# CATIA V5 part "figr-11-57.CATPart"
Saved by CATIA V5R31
Part number: Part1
Bounding box of the stored display mesh (mm): x -55 to 55, y -105 to 155, z -20 to 14.953
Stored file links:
  D:\PROJECTS\Project 2021\US EDITION\CATIA V5 6R 2021\Resources\Part Files\c11_catia_v5_6r2021_prt\figr-11-57.CATPart
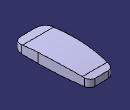
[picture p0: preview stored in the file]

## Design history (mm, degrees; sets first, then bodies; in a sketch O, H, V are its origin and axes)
Set1
  Extrude1: Element1 Sketch2, Lim1 50, Lim2 50, Direction yz-plane
  Sketch1 on xy-plane, origin (0, 0, 0), H (1, 0, 0), V (0, 1, 0)
    arc A1 centre (25, -75) radius 25 from (25, -100) to (50, -75) ccw
    line L1 (50, -75) -> (50, -15)
    point P4 (50, -15)
    arc A2 centre (-950, -15) radius 1000 from (50, -15) to (38.3367, 137.2843) ccw
    line L2 (23.5117, 150) -> (-23.5117, 150)
    line L3 (25, -100) -> (-25, -100)
    arc A3 centre (-25, -75) radius 25 from (-25, -100) to (-50, -75) cw
    line L4 (-50, -75) -> (-50, -15)
    point P9 (-50, -15)
    arc A4 centre (950, -15) radius 1000 from (-50, -15) to (-38.3367, 137.2843) cw
    reference projected line E1 (-50, -100) -> (50, -100) from edge of Extrude1
    axis line L5 (0, 170.4214) -> (0, -120.6595)
    point P11 (0, 170.4214)
    reference projected line E2 (50, -70) -> (50, 129.9971) from edge of Extrude1
    reference projected line E3 (-50, 129.9971) -> (-50, -70) from edge of Extrude1
    reference projected line E4 (-50, -100) -> (50, -100) from edge of Extrude1
    reference projected line E5 (50, 150) -> (-50, 150) from edge of Extrude1
    arc A5 centre (-23.5117, 135) radius 15 from (-38.3367, 137.2843) to (-23.5117, 150) cw
    arc A6 centre (23.5117, 135) radius 15 from (38.3367, 137.2843) to (23.5117, 150) ccw
    distance E4 P4 = 85
    radius A2 = 1000
    radius A5 = 15
    radius A6 = 15
    radius A1 = 25
    radius A3 = 25
    radius A4 = 1000
    tangency: L1 A1, A2 L1, L3 A1, A3 L3, A4 L4, L5 A3, A5 L2, A5 A4, A6 A2, A6 L2, A3 L4
    horizontal: L2 H
    coincidence: L3 E1, P11 V, L1 E2, L4 E3, L2 E5
    symmetry: P4 P9 L5
  Extrude2: Element1 Sketch1, Lim1 50, Lim2 20, Direction xy-plane
  Split1: ToCut Extrude2, Cutting Extrude1
  Split2: ToCut Extrude1, Cutting Split1
  Join1: Elements (Split2; Split1)
Body1 (main body)
  Sketch2 on yz-plane, origin (0, 0, 0), H (0, 1, 0), V (0, 0, 1)
    point P1 (-100, 0)
    line L1 (-100, 0) -> (-70, 3.8724)
    point P2 (-70, 3.8724)
    arc A1 centre (26.0141, -739.9564) radius 750 from (-70, 3.8724) to (129.9971, 2.8003) cw
    point P4 (129.9971, 2.8003)
    line L2 (129.9971, 2.8003) -> (150, 0)
    point P5 (150, 0)
    distance P1 P5 = 250
    distance P1 O = 100
    radius A1 = 750
    distance P2 P4 = 200
    distance P2 V = 70
    coincidence: P1 H, P5 H
    tangency: A1 L1, L2 A1
  ThickSurface1: BotOffset 0, Surface Join1, TopOffset 5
